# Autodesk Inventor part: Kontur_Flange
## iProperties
Created: 2007-02
Part Number: Kontur_Flange
Document SubType Name: Sheet Metal
Designer: Eng1
Density: 1 g/cm^3
Sheet Metal Rule: Default
Author: Eng1
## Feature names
1. Plate1
